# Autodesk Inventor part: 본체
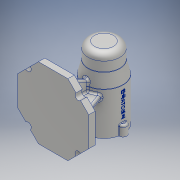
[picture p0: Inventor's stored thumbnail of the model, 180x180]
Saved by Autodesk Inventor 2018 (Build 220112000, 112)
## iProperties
Created: 2019-12
Part Number: 본체
Material: 알루미늄 6061
Document SubType Name: Modeling
Designer: Administrator
Density: 2.7 g/cm^3
Appearance: 알루미늄 - 평지
Mass: 724.648 g
Surface Area: 718.71 cm^2
Volume: 268.388 cm^3
Author: Administrator
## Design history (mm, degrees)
sketch "스케치1"
  geometry: L1 (56, -23.196)-(23.196, -56); L2 (23.196, -56)-(-23.196, -56); L3 (-23.196, -56)-(-56, -23.196); L4 (-56, -23.196)-(-56, 23.196); L5 (-56, 23.196)-(-23.196, 56); L6 (-23.196, 56)-(23.196, 56); L7 (23.196, 56)-(56, 23.196); L8 (56, 23.196)-(56, -23.196); L9 (4, 38)-(-4, 38); L10 (-36, 4)-(-36, -4); L11 (4, -31)-(-4, -31); L12 (36, -4)-(36, 4); L13 (-36, 4)-(-4, 4); L14 (4, 4)-(36, 4); L15 (-36, -4)-(-4, -4); L16 (4, -4)-(36, -4); L17 (4, -31)-(4, -4); L18 (4, 4)-(4, 38); L19 (-4, -31)-(-4, -4); L20 (-4, 4)-(-4, 38)
  constraints: 40 end point, 2 horizontal, 1 perpendicular, 1 vertical
extrude "돌출1" new body sketch "스케치1" distance "d12" = 10; taper "d13" = 0 deg
sketch "스케치11"
  geometry: L1 (-23.196, -56)-(23.196, -56) reference; L2 (23.196, 56)-(-23.196, 56) reference; L3 (-56, 23.196)-(-56, -23.196) reference; L4 (56, -23.196)-(56, 23.196) reference; L5 (-4, -38)-(4, -38); L6 (-4, 31)-(4, 31); L7 (36, 4)-(36, -4); L8 (-36, 4)-(-36, -4); L9 (-36, -4)-(-4, -4); L10 (4, -4)-(36, -4); L11 (-36, 4)-(-4, 4); L12 (4, 4)-(36, 4); L13 (-4, -38)-(-4, -4); L14 (-4, 4)-(-4, 31); L15 (4, -38)-(4, -4); L16 (4, 4)-(4, 31)
  constraints: 24 end point, 2 perpendicular, 2 vertical, 1 horizontal
extrude "돌출5" join sketch "스케치11" distance "d63" = 60; taper "d64" = 0 deg
sketch "스케치12"
  geometry: L1 (0, 0)-(0, 60) reference; L2 (0, 0)-(31.572, 67.706); L3 (14.804, 0)-(-18, 0) reference; L4 (31.572, 67.706)-(-13.584, 67.706); L5 (-13.584, 67.706)-(0, 0); 1 further point
  constraints: 6 end point, 1 horizontal
  dimensions: "d65" = 115 deg angle of L3 L2
extrude "돌출6" cut sketch "스케치12" distance "d66" = 60; taper "d67" = 0 deg
sketch "스케치14"
  geometry: L1 (0, 0)-(0, 60) reference; L2 (0, 0)-(25.068, 68.874); L3 (72, 0)-(72, 60) reference; L4 (72, 0)-(46.126, 71.088); L5 (12.804, 0)-(-20, 0) reference; L6 (92, 0)-(59.196, 0) reference; L7 (25.068, 68.874)-(-16.458, 68.874); L8 (-16.458, 68.874)-(0, 0); L9 (46.126, 71.088)-(87.802, 61.365); L10 (87.802, 61.365)-(72, 0); 1 further point
  constraints: 12 end point, 1 horizontal
  dimensions: "d75" = 110 deg angle of L5 L2; "d76" = 110 deg angle of L6 L4
extrude "돌출7" cut sketch "스케치14" distance "d77" = 60; taper "d78" = 0 deg
sketch "스케치16"
  geometry: L1 (0, -56)-(10, -56) reference; L2 (80, -56)-(110, -56); L3 (110, -56)-(110, 11); L4 (80, -56)-(80, 56); L5 (80, 56)-(105, 56); L6 (105, 56)-(105, 31); L7 (105, 31)-(110, 11); L8 (80, 77.157)-(80, -78.468); 1 further point
  constraints: 14 end point, 2 perpendicular, 2 vertical, 1 horizontal, 1 point on line
  dimensions: "d81" = 30 distance of L2.start L2.end; "d82" = 67 distance of L2.end L3.end; "d83" = 112 distance of L2.start L4.end; "d84" = 25 distance of L4.end L5.end; "d85" = 25 distance of L5.end L6.end
revolve "회전4" sketch "스케치16" stored, may be unused: angle "d86" = 90 deg
sketch "스케치17"
  geometry: L1 (50, -56)-(110, -56) reference; L2 (80, -56)-(101, -56); L3 (101, -56)-(101, -41); L4 (101, -41)-(104, -41); L5 (104, -41)-(104, 13); L6 (104, 13)-(101, 13); L7 (101, 13)-(101, 25); L8 (101, 25)-(97.5, 25); L9 (97.5, 25)-(97.5, 43); L10 (97.5, 43)-(96, 43); L11 (96, 43)-(96, 47); L12 (96, 47)-(90.5, 47); L13 (90.5, 47)-(90.5, 50); L14 (90.5, 50)-(80, 50); L15 (80, 50)-(80, -56); L16 (80, -74.417)-(80, 91.55); 1 further point
  constraints: 30 end point, 11 perpendicular, 2 point on line, 2 vertical, 1 horizontal, 1 midpoint
  dimensions: "d89" = 21 distance of L2.start L2.end; "d90" = 15 distance of L2.end L3.end; "d91" = 3 distance of L3.end L4.end; "d92" = 54 distance of L4.end L5.end; "d93" = 3 distance of L5.end L6.end; "d94" = 12 distance of L6.end L7.end; "d95" = 3.5 distance of L7.end L8.end; "d96" = 18 distance of L8.end L9.end; "d97" = 1.5 distance of L9.end L10.end; "d98" = 4 distance of L10.end L11.end; "d99" = 5.5 distance of L11.end L12.end; "d100" = 3 distance of L12.end L13.end
revolve "회전5" sketch "스케치17" stored, may be unused: angle "d101" = 90 deg
fillet "모깎기2" dims "d102" = 10
fillet "모깎기3" dims "d103" = 3
fillet "모깎기4" dims "d104" = 3
fillet "모깎기6" dims "d106" = 0.3
sketch "스케치18"
  geometry: C1 r 6 at (0, 30); C2 r 6 at (30, 0); C3 r 6 at (0, -30); C4 r 6 at (-30, 0); A1 r 30 centre (0, 0) between (6.381, -29.314) and (-6.381, -29.314) reference; 1 further point
  constraints: 4 centre point, 1 point on circle
  dimensions: "d107" = 6 radius of C1; "d108" = 6 radius of C2; "d109" = 6 radius of C3; "d110" = 6 radius of C4
extrude "돌출8" join sketch "스케치18" distance "d111" = 16; taper "d112" = 0 deg
sketch "스케치19"
  geometry: C1 r 21 at (0, -30) reference; A1 r 30 centre (0, -30) between (5.97, -59.4) and (29.4, -35.97) reference; A2 r 6 centre (30, -30) between (29.4, -35.97) and (29.4, -24.03) reference; A3 r 30 centre (0, -30) between (29.4, -24.03) and (5.97, -0.6) reference; A4 r 6 centre (0, 0) between (5.97, -0.6) and (-5.97, -0.6) reference; A5 r 30 centre (0, -30) between (-5.97, -0.6) and (-29.4, -24.03) reference; A6 r 6 centre (-30, -30) between (-29.4, -24.03) and (-29.4, -35.97) reference; A7 r 30 centre (0, -30) between (-29.4, -35.97) and (-5.97, -59.4) reference; A8 r 6 centre (0, -60) between (-5.97, -59.4) and (5.97, -59.4) reference; 5 further points
  constraints: 4 coincident
hole "구멍1" sketch "스케치19" at (-30, -30), (0, -60), (30, -30), (0, 0) diameter "d113" = 3.242; stored, may be unused: countersink angle "d117" = 90 deg, drill point angle "d119" = 118 deg; dims "d114" = 8, "d115" = 4, "d116" = 2, "d118" = 11
sketch "스케치20"
  geometry: L1 (-23.196, -56)-(-56, -23.196) reference; L2 (-39.598, -39.598)-(0, 0); L3 (56, -23.196)-(23.196, -56) reference; L4 (39.598, -39.598)-(0, 0); L5 (0, 0)-(39.598, 39.598); L6 (23.196, 56)-(56, 23.196) reference; L7 (0, 0)-(-39.598, 39.598); L8 (-56, 23.196)-(-23.196, 56) reference; C1 r 5 at (39.598, -39.598); C2 r 5 at (-39.598, -39.598); C3 r 5 at (-39.598, 39.598); C4 r 5 at (39.598, 39.598)
  constraints: 8 end point, 4 centre point, 4 coincident, 4 midpoint, 2 perpendicular
  dimensions: "d120" = 5 radius of C1; "d121" = 5 radius of C2; "d122" = 5 radius of C3; "d123" = 5 radius of C4
extrude "돌출9" cut sketch "스케치20" distance "d124" = 16; taper "d125" = 0 deg
node "작업 평면1"
sketch "스케치21"
  geometry: L1 (6, -33.5)-(-6, -33.5) reference; L2 (5.97, -33.5)-(29.4, -33.5) reference; 4 further points
  constraints: 1 midpoint, 1 vertical alignment, 1 other
  dimensions: "d126" = 41 distance from line of L2 point (0, 7.5)
feature "엠보싱1" sketch "스케치21" dims "d127" = 0.5, "d128" = 0
fillet "모깎기7" dims "d129" = 3
fillet "모깎기8" dims "d130" = 1
fillet "모깎기9" dims "d131" = 3
fillet "모깎기10" dims "d132" = 3
fillet "모깎기11" dims "d133" = 3
chamfer "모따기1" distance "d134" = 1; stored, may be unused: second distance "d135" = 2, angle "d136" = 45 deg
node "솔리드1"
node "투영된 루프7"
